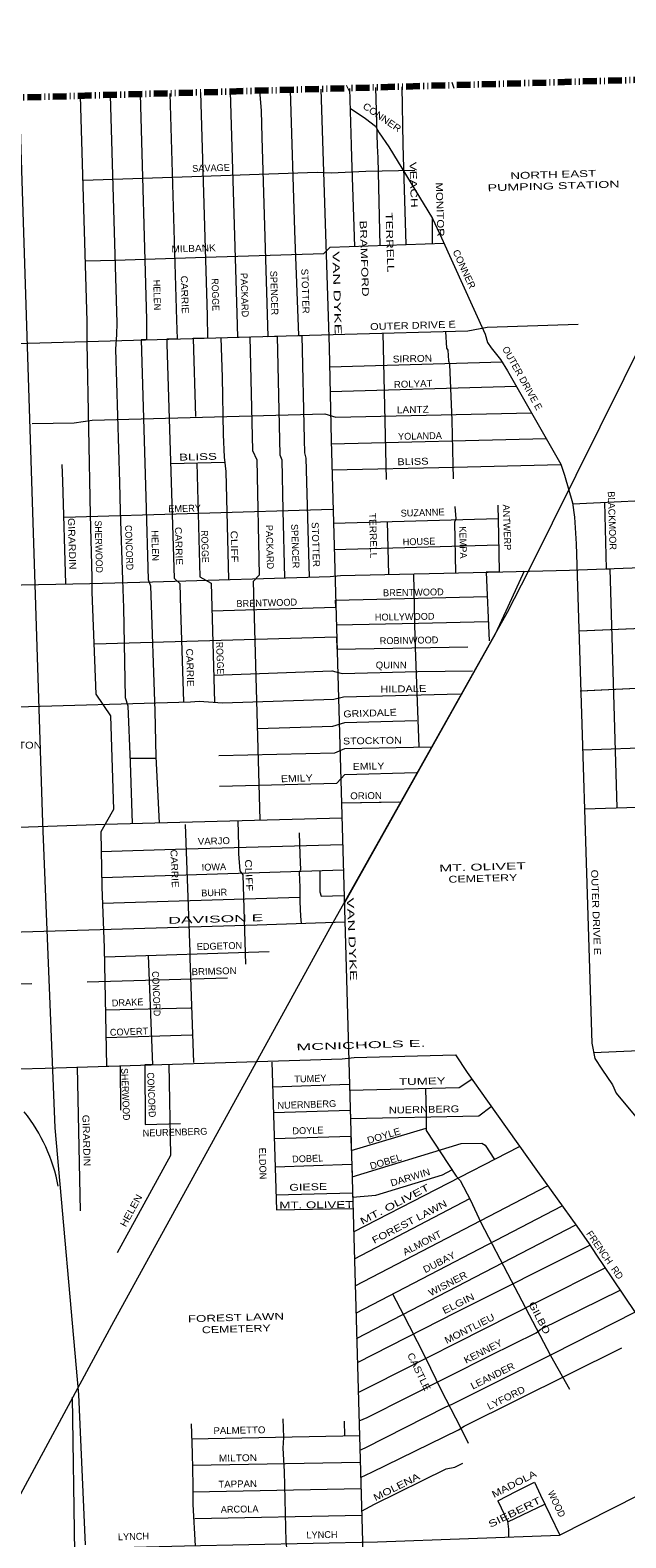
# Model space of a CAD drawing. Extents: x 34705 to 138605, y 34275 to 143551.
# Drawn here: x 102735 to 109243, y 126812 to 143301 of the extents above; entities that cross this region are included whole.
import ezdxf
from ezdxf.enums import TextEntityAlignment as Align

# ---------------------------------------------------------------- set-up
doc = ezdxf.new("R2010")
doc.units = 0
doc.header["$LTSCALE"] = 30
doc.linetypes.add('DASH_DOUBLE_DOT', pattern=[9.2, 5, -1.2, 0.3, -1.2, 0.3, -1.2])
for name, color, linetype, lineweight in [('1', 7, 'Continuous', 13), ('11', 7, 'Continuous', 13), ('50', 7, 'Continuous', 13), ('59', 7, 'DASH_DOUBLE_DOT', 106)]:
    doc.layers.add(name, color=color, linetype=linetype, lineweight=lineweight)

msp = doc.modelspace()

# ---------------------------------------------------------------- linework, layer by layer
at = {"layer": '1'}
for p, q in [((105241.22, 142636.71), (105241.23, 142636.69)), ((105577.19, 142646.29), (105577.19, 142646.27)), ((106225.39, 142664.78), (106225.39, 142664.76)), ((106509.93, 142672.9), (106509.93, 142672.88)), ((106798.42, 142681.13), (106798.42, 142681.11)), ((103282.09, 142580.82), (103282.09, 142580.81)), ((103608.22, 142590.12), (103608.22, 142590.11)), ((103936.04, 142599.48), (103936.04, 142599.46)), ((104597.13, 142618.33), (104597.13, 142618.32)), ((107125.24, 141252.45), (107125.24, 140965.6)), ((106588.83, 139987.07), (106625.18, 138387.12)), ((106006.47, 139620.57), (107895.32, 139674.21)), ((106011.62, 139347.51), (108047.5, 139407.06)), ((106022.69, 138778.23), (108372.47, 138836.55)), ((104269.01, 138562.85), (104861.84, 138574.95)), ((103104.63, 137975.65), (106043.11, 138062.79)), ((106047.45, 137910.61), (107847.77, 137958.8)), ((106636.48, 137926.38), (106648.38, 137348.73)), ((106055.76, 137619.77), (107853.69, 137673.55)), ((108770.55, 135431.09), (111396.79, 135518.47)), ((103831.38, 135339.63), (104104.63, 135339.63)), ((106134.79, 134850.9), (106755.8, 134862.73)), ((106145.33, 134851.1), (106780.48, 134863.2)), ((103520.34, 134033.98), (106155.73, 134117.16)), ((103526.15, 133754.82), (105679.75, 133819.22)), ((103549.41, 133167.42), (105345.92, 133225.58)), ((103359.03, 132891.89), (104891.72, 132937.53)), ((101502.89, 132835.92), (102751.71, 132874.45)), ((103564.13, 132283.14), (104502.9, 132312.49)), ((103248.56, 131961.25), (103281.01, 130390.15)), ((106268.74, 130157.86), (108081.19, 131092.77)), ((106285.57, 129568.32), (108387.63, 130663.68)), ((106277.11, 129864.47), (107537.35, 130523.14)), ((106294.05, 129271.02), (108547.04, 130441.73)), ((106302.01, 128992.23), (108696.67, 130233.82)), ((106166.78, 128088.93), (106167.87, 127927.46)), ((104499.25, 127896.76), (106332.27, 127932.02)), ((104507.95, 127606.16), (106340.57, 127641.41)), ((104511.93, 127315.08), (106348.87, 127350.42)), ((107952.24, 126985.55), (108358.24, 127182.27)), ((104534.64, 127024.47), (106357.17, 127059.53))]:
    msp.add_line(p, q, dxfattribs=at)
for points in [[(105240.21, 142636.66), (105258.81, 142422.75), (105265.22, 142127.75), (105330.55, 139952.31), (105434.27, 139955.26), (105463.96, 138658.25), (105483.19, 138600.53), (105496.02, 138049), (105515.21, 137309.76)], [(105576.18, 142646.24), (105624.24, 141108.06), (105666.52, 139961.86), (105704.77, 139962.95), (105726.81, 138824.99), (105733.22, 138677.49), (105746.05, 138619.77), (105784.05, 137317.69)], [(105908.84, 142655.73), (106002.49, 139831.85), (106021.72, 138812.17), (106489.73, 122415.45), (106528.19, 121498.37), (106553.84, 121113.59), (107079.54, 120098.72), (107093.68, 120071.85)], [(106224.37, 142664.73), (106241.41, 142042.82), (106247.23, 141909.04), (106276.87, 140936.34)], [(106508.91, 142672.85), (106526.33, 142037.01), (106532.15, 141903.22), (106555.92, 140945.96)], [(106797.4, 142681.08), (106805.43, 142054.46), (106811.25, 141920.67), (106840.66, 140955.79)], [(103281.07, 142580.78), (103353.13, 140117.24), (103354.28, 139882.14), (103389.99, 137999.3), (103409.23, 137316.31), (103409.23, 137155.99), (103454.1, 136040.1), (103614.38, 135802.82), (103646.44, 134776.72), (103505.39, 134533.02), (103518.22, 133930.18), (103543.86, 133266.43), (103569.91, 131971.03), (103716.95, 131975.49), (103722.94, 131489.9)], [(103607.2, 142590.08), (103680.1, 140098), (103678.49, 139972.94), (103665.67, 139812.61), (103710.55, 138355.24), (103716.96, 138041), (103742.6, 137290.66), (103755.42, 136982.83), (103774.66, 136001.62), (103800.3, 135911.84), (103827.55, 135292.98), (103850.48, 134623.9)], [(103935.02, 142599.43), (104007.06, 140136.48), (104005.18, 139914.61), (103946.92, 139912.95), (103999.04, 138198.11), (104024.69, 137293.86), (104050.33, 137223.32), (104095.21, 135854.12), (104108.03, 135353.9), (104144.4, 134632.18)], [(104261.52, 142608.74), (104334.02, 140130.07), (104340.55, 139924.15), (104229.28, 139920.98), (104229.84, 139865.52), (104306.77, 137306.69), (104370.88, 137248.97), (104377.3, 136966.79), (104409.24, 135953.78)], [(104596.11, 142618.29), (104667.4, 140181.37), (104672.31, 139933.59), (104515.43, 139929.12), (104540.84, 139076.62)], [(104921.4, 142627.57), (104994.36, 140200.61), (105000.11, 139942.91), (105133.99, 139946.72), (105165.85, 138704.75), (105210.73, 138602.14), (105236.38, 137338.75), (105172.26, 137271.42), (105223.55, 135443.68), (105243.22, 134663.15)], [(106230.31, 142447.99), (106398.41, 142333.65), (106508.89, 142252.22), (106549.59, 142176.6), (106654.25, 142025.37), (107131.06, 141240.14), (107229.91, 141030.74), (107706.71, 139977.94), (107729.97, 139884.88), (107770.67, 139826.71), (107875.33, 139698.75), (107950.92, 139576.6), (108532.39, 138555.8), (108573.09, 138433.65), (108660.31, 138131.19), (108683.57, 137974.15), (108701.02, 137683.32), (108869.64, 132221.58), (108904.53, 132052.9), (108980.12, 131936.57), (109096.41, 131767.89), (109137.12, 131674.83), (109369.7, 131394.19)], [(103313.94, 141659.99), (104290.68, 141694.88), (105872.08, 141747.22), (106023.24, 141741.41), (106401.15, 141758.85), (106936.03, 141770.49)], [(103343.01, 140778.89), (103662.77, 140784.71), (104651.15, 140819.6), (105941.85, 140857.4), (106011.61, 140927.19), (107257.34, 140970.16)], [(90124.26, 139559.75), (94346.64, 139649.89), (98992, 139772.02), (106174.4, 139976.31), (107517.43, 140011.2), (107726.73, 140051.91), (108720.92, 140086.81)], [(107273.19, 140004.85), (107282.24, 139823.81), (107299.68, 139800.54), (107305.5, 139684.21), (107317.13, 139649.31), (107340.38, 139032.76), (107352.01, 138549.98), (107357.83, 138392.94)], [(104817.86, 139937.72), (104832.48, 139506.39), (104845.3, 138877.9), (104855.55, 138630.68), (104873.28, 138473.62), (104902.91, 137291.71)], [(102755.8, 138999.24), (103215.15, 139005.59), (103412.77, 139034.14), (105953.47, 139103.93), (105953.47, 139103.93), (106075.57, 139069.03), (108213.42, 139115.78)], [(103082.26, 138550.83), (103087.08, 138369.66), (103119.91, 137244.96)], [(104555.29, 138568.69), (104588.86, 137322.73), (104710.67, 137252.18), (104748.75, 135950.51)], [(106030.82, 138493.3), (107366.27, 138522.34), (108533.51, 138552.44)], [(108664.22, 138121.05), (109867.71, 138179.21), (111303.76, 138237.37), (111320.11, 138237.28), (111322.59, 138165.33), (114938.93, 138286.81), (115270.33, 138298.44), (115421.49, 138315.89), (115595.91, 138344.97), (115793.58, 138379.86), (116002.89, 138408.94), (116590.1, 138426.39), (116700.56, 138420.57), (118925.85, 138493.26), (119005.88, 138494.1), (118966.04, 138412.22), (119013.06, 138411.84), (121049.49, 138481.62), (122550.35, 138528.72)], [(107375.27, 138090.48), (107386.9, 137956.7), (107369.46, 137921.8), (107381.16, 137365.65)], [(107844.24, 138107.91), (107852.08, 137776.38), (107858.06, 137376.67), (107717.8, 137373.43), (107749.55, 136622.18)], [(109008.41, 138137.68), (109026.36, 137409.71), (109067.79, 137410.34), (109143.51, 134796.33)], [(89232.24, 136885.29), (90112.2, 136931.38), (91366.5, 136935.99), (91366.5, 136935.99), (92803.93, 136935.99), (93200.15, 136949.81), (94080.12, 136972.86), (96283.49, 137037.38), (97052.88, 137051.21), (97647.21, 137074.25), (99279.05, 137128.15), (100742.47, 137173.13), (101449.66, 137193.58), (102455.25, 137230.38), (103387.26, 137250.83), (104070.94, 137267.18), (106012.63, 137324.43), (106127.09, 137336.7), (107898.11, 137377.59), (108625.74, 137393.94), (111271.54, 137492.08)], [(108133.14, 137382.87), (107955.18, 136995.41), (107817.1, 136696.16), (106166.26, 133748.33)], [(106921.39, 137355.04), (106939.17, 136649.43), (106979.87, 135462.85)], [(104719.52, 136949.85), (106073.67, 136992.01), (106071.57, 137065.46), (107726.73, 137107.65)], [(106079.23, 136797.06), (106976.73, 136816.86), (107740.56, 136834.49)], [(108730.42, 136730.91), (110361.9, 136800.85), (111368.15, 136842.06)], [(108733.99, 136731.06), (110361.9, 136800.85), (111356.09, 136841.56)], [(103436.03, 136590.04), (106082.95, 136666.72), (106086.82, 136531.37), (107515.21, 136557.33)], [(104744.17, 136246.9), (106029.05, 136293.43), (106034.87, 136293.43), (106127.89, 136270.17), (106145.33, 136264.35), (106970.92, 136287.62), (107568.73, 136293.98)], [(92946.94, 135660.23), (93342.28, 135666.05), (93342.28, 135660.23), (93505.08, 135747.47), (95619.1, 135806.18), (95623.65, 135694.55), (97684.58, 135762.73), (99091.56, 135791.81), (100777.6, 135844.15), (100969.46, 135844.15), (102463.65, 135896.5), (104488.36, 135956.11), (104581.38, 135961.93), (104837.19, 135944.48), (106052.31, 135985.19), (106156.96, 136008.45), (107431.31, 136044.53)], [(108745.62, 136076.79), (109745.62, 136123.31), (110704.92, 136164.02), (111390.97, 136181.47)], [(108750.61, 136077.02), (109745.62, 136123.31), (110704.92, 136164.02), (111390.9, 136181.47)], [(105217.33, 135665.05), (106040.68, 135688.58), (106174.4, 135729.29), (106959.29, 135752.56)], [(104796.5, 135368.71), (106063.94, 135397.79), (106174.4, 135444.32), (107110.18, 135461.65)], [(104802.31, 135031.39), (106087.19, 135066.29), (106174.4, 135159.34), (106956.49, 135182.69)], [(108790.49, 134785.25), (115475.27, 134995.04), (117335.18, 135061.27)], [(108890.69, 132119.83), (110218.62, 132177.59), (111463.66, 132219.8), (111598.19, 132244.87), (113708.42, 133273.94), (116745.85, 134738.39), (117107.22, 134743.67), (117260.22, 134791.17), (117560.93, 134785.89), (119249.54, 134800.95), (119957.59, 134818.33), (120035.78, 134827.02), (120789.59, 134833.38), (121930.43, 134865.05), (122072.88, 134859.77), (123502.56, 134875.6), (123708.58, 134772.56)], [(83101.01, 133486.56), (83891.71, 133858.78), (85025.43, 133905.3), (85083.57, 133934.38), (86840.83, 134002.71), (86990.55, 133998.36), (87997.81, 134043.42), (88660.6, 134066.69), (89340.84, 134089.95), (89858.28, 134107.4), (90311.77, 134159.74), (90515.26, 134258.61), (90840.84, 134305.14), (93673.68, 134351.66), (95138.8, 134363.3), (95679.5, 134380.74), (97726.73, 134441.09), (98308.13, 134452.72), (100831.39, 134522.51), (103555.22, 134615.57), (106139.42, 134688.42)], [(104428.58, 134613.19), (104479.87, 133221.54), (104479.87, 133151), (104518.34, 132009.46)], [(105004.8, 134656.43), (105011.99, 134375.9), (105011.99, 134292.53), (105024.81, 134106.55), (105056.87, 134061.66), (105087.62, 133085.11)], [(103508.71, 134318.96), (104438.94, 134348.04), (106147.79, 134395.33)], [(105675.53, 134523.4), (105681.94, 134286.12), (105688.35, 134119.38), (105675.53, 134087.31), (105681.94, 133926.98), (105681.94, 133766.66), (105688.35, 133612.74), (105695.63, 133532.55)], [(105899.91, 134109.09), (105899.91, 133875.68), (105912.73, 133830.79), (106163.72, 133837.39)], [(95130.25, 130321.18), (95381.61, 130325.96), (95576.64, 130393.64), (96452.28, 130819.66), (97383.65, 131301.42), (98108.05, 131675.68), (101094.19, 133205.57), (101336.98, 133321.03), (101452.41, 133392.7), (101671.32, 133392.7), (102639.49, 133440.47), (105214.69, 133516.12), (106171.95, 133548.83)], [(104024.82, 133182.81), (104071.67, 131986.28), (103986.02, 131983.68), (103992.63, 131331.27), (104377.3, 131344.1)], [(103561.03, 132585.84), (104485.45, 132609.1), (104491.27, 132609.1)], [(89151.86, 131581.25), (90043.44, 131623.47), (90222.81, 131655.13), (92165.54, 131723.74), (95067.12, 131739.57), (95420.59, 131739.57), (95721.29, 131755.4), (98262.81, 131813.45), (98568.79, 131829.28), (100441.63, 131866.22), (101676.12, 131897.89), (102335.57, 131934.83), (102900.06, 131950.66), (106145.2, 132049.31), (106275.51, 132066.69), (107380.6, 132092.9)], [(107380.6, 132092.9), (107509.01, 131900.23), (107729.97, 131586.13), (108276.55, 130818.35), (108706.83, 130219.24), (108840.57, 130027.3), (108921.97, 129905.15), (109090.6, 129655.04), (109352.26, 129265.33), (109520.89, 129026.85), (109672.07, 128817.45), (109799.99, 128637.14), (110038.39, 128323.04), (110347.56, 127910.69)], [(104248.73, 131991.66), (104268.31, 130992.99), (103685.3, 129928.8)], [(105374.21, 132014.28), (105425.49, 130398.17), (106015.31, 130411), (106261.38, 130415.72)], [(105382.78, 131744.16), (106222.62, 131773.5), (106224.5, 131707.7), (107422.29, 131736.45), (107559.04, 131829.11)], [(107055.03, 131728), (107061.28, 131446.54), (107061.28, 131312.75), (107061.28, 131266.22), (107389.18, 130767.47), (107434.67, 130721.97), (107545.84, 130504.6), (107657.02, 130261.95), (107990.55, 129625), (108420.1, 128806.07), (108627.29, 128437.04)], [(105391.72, 131462.33), (106230.7, 131490.67), (106233.29, 131399.77), (107635.14, 131427.93), (107769.83, 131530.14)], [(105400.68, 131180.2), (106238.88, 131203.93), (106243.3, 131049.26), (107061.28, 131293.95)], [(105410.48, 130871.28), (106247.54, 130900.63), (106251.58, 130758.89), (107444.01, 131123.76), (107669.89, 131128.11), (107704.65, 131106.38), (107806.52, 130951.09)], [(105420.26, 130563.11), (106256.49, 130587.1), (106257.89, 130538), (106510.08, 130558.88), (107239.85, 130780.49), (107343.46, 130837.02)], [(106309.47, 128731), (107389.34, 129281.12), (108850.73, 130012.05)], [(106324.83, 128403.6), (106477.61, 128482.48), (108005.37, 129256.47), (108291.21, 129399.43), (109015.35, 129766.65)], [(106327.76, 128090.16), (106418.47, 128127.53), (107758.96, 128807.85), (108261.64, 129054.34), (108315.85, 129093.78), (109180.46, 129521.2)], [(106695.19, 129479.47), (106817.06, 129242.06), (106875.21, 129131.55), (107049.65, 128788.37), (107224.09, 128427.74), (107433.42, 128026.4), (107520.64, 127846.09)], [(106336.86, 127771.32), (106393.83, 127797.22), (107275.99, 128245.84), (107344.98, 128275.42), (108379.92, 128793.06), (108453.85, 128827.57), (109342.27, 129279.46)], [(106345.39, 127472.47), (106467.75, 127531.01), (107413.98, 127994.42), (107478.05, 128033.86), (109198.02, 128891.66)], [(104492.69, 128060.59), (104505.52, 127739.94), (104511.93, 127387.22), (104511.93, 127175.58), (104538.35, 126726.21)], [(105496.02, 128113.5), (105502.43, 127908.28), (105496.02, 127792.85), (105508.84, 127536.32), (105528.07, 126773.16), (105540.89, 126670.55), (105540.89, 126484.57), (105553.72, 126119.02), (105983.26, 126131.85), (106383.49, 126137.66), (106382.09, 126186.48), (106858.57, 126206.46)], [(103316.6, 126694.24), (104421.29, 126723.75), (106530.59, 126768.12), (108517.91, 126840.83), (110257.59, 127723.28), (110321.66, 127807.08), (110347.56, 127910.69)], [(106355.88, 127104.81), (106497.32, 127180.99), (107280.92, 127565.52), (107374.55, 127585.24), (107463.26, 127629.61)], [(107846.01, 127216.97), (108049.73, 127323.96), (108243.48, 127422.56)], [(108243.48, 127422.56), (108311.43, 127280.44), (108520.42, 126842.1)], [(107846.01, 127216.97), (107950.92, 126995.42), (107962.55, 126908.18), (107962.55, 126820.51)]]:
    msp.add_lwpolyline(points, dxfattribs=at)
at = {"layer": '50'}
msp.add_line((103193.88, 128351.06), (103217.66, 126651.13), dxfattribs=at)
for points in [[(102381.37, 126834.33), (103625.89, 129138.56), (106032.14, 133515.49), (107949.49, 136936.41), (108177.8, 137385.22), (110790.54, 142647.36)], [(103340.26, 126734.43), (103267.19, 128379.83), (103009.15, 131294.52), (102874.51, 134633.08), (102617.68, 142561.85)]]:
    msp.add_lwpolyline(points, dxfattribs=at)
msp.add_arc((101213, 130316.33), 1860.19, 10.55696, 38.38477, dxfattribs=at)
at = {"layer": '59'}
msp.add_lwpolyline([(131989.06, 109708.72), (126856.28, 120352.83), (127983.73, 120601.28), (129321.71, 120998.46), (130612.42, 121494.12), (133722.19, 123216.65), (134563.84, 124776.42), (136438.38, 130047.1), (136736.54, 131235.05), (136773.12, 131974.15), (125584.57, 138103.26), (128512.62, 143301.1), (34921.35, 140631.52)], dxfattribs=at)

# ---------------------------------------------------------------- texts
at = {"layer": '11'}
for s, rotation, width, p in [('CONNER', 325.489, 1.1, (106558.33, 142316.68)), ('VEACH            ', 271.866, 1.45, (106895.29, 141367.2)), ('PUMPING STATION', 1.665, 1.55, (108454.7, 141560.15)), ('NORTH EAST', 1.665, 1.45, (108451.07, 141685.09)), ('MONITOR  ', 271.865, 1.25, (107176.79, 141303.98)), ('BRAMFORD            ', 271.865, 1.45, (106356.29, 140560.05)), ('TERRELL              ', 271.866, 1.45, (106637.56, 140695.14)), ('MILBANK', 1.698, 1.1, (104521.36, 140876.69)), ('VAN DYKE', 271.7, 1.8, (106050.48, 140425.92)), ('CONNER', 294.365, 1.05, (107442.95, 140672.31)), ('STOTTER', 271.702, 1.05, (105704.89, 140445.69)), ('CARRIE', 271.7, 1.1, (104386.58, 140406.67)), ('ROGGE', 271.7, 0.95, (104721.75, 140407.33)), ('OUTER DRIVE E', 1.714, 1.2, (106918.25, 140034.69)), ('SIRRON', 1.512, 1.1, (106911.73, 139671.28)), ('ROLYAT', 1.865, 1.05, (106920.07, 139395.3)), ('LANTZ', 1.297, 1.1, (106916.12, 139114.24)), ('BLISS       ', 1.526, 1.45, (104710.88, 138601.77)), ('BLISS', 1.36, 1.2, (106917.63, 138546.42)), ('TERRELL', 271.607, 1.1, (106445.36, 137772.56)), ('GIRARDIN', 271.598, 1.15, (103155.37, 137682.7)), ('SHERWOOD', 271.408, 0.95, (103447.4, 137650.95)), ('CONCORD', 271.984, 0.95, (103779.34, 137640.51)), ('CARRIE', 271.644, 1.1, (104322.44, 137658.3)), ('STOTTER', 271.814, 1.05, (105817.93, 137674.78)), ('ROGGE', 271.498, 0.95, (104607.72, 137653.6)), ('CLIFF', 271.528, 1.25, (104929.47, 137652.77)), ('CARRIE', 271.806, 1.1, (104445.21, 136328.45)), ('ROGGE', 272.153, 0.95, (104772.72, 136432.18)), ('HILDALE', 0.998, 1.2, (106812.46, 136060.03)), ('GRIXDALE', 2.001, 1.15, (106449.73, 135794.82)), ('STOCKTON ', 0.999, 1.15, (106490.26, 135494.17)), ('EMILY', 0.999, 1.15, (106432.57, 135213.84)), ('EMILY', 1.883, 1.15, (105648.95, 135081.15)), ('ORION', 0.8, 1.05, (106405.28, 134891.69)), ('VARJO', 1.585, 1.05, (104743.09, 134395.85)), ('CARRIE', 272.3, 1.1, (104275.63, 134129.34)), ('CLIFF', 272.3, 1.25, (105087.6, 134056.64)), ('MT. OLIVET', 1.665, 1.7, (107678.61, 134112.34)), ('CEMETERY', 1.665, 1.35, (107682.24, 133987.39)), ('OUTER DRIVE E', 271.985, 1.2, (108879.69, 133651.3)), ('VAN DYKE', 272.301, 1.8, (106213.62, 133357.48)), ('DAVISON E', 1.683, 1.9, (104763.99, 133542.27)), ('CONCORD', 272.3, 0.95, (104076.08, 132761.84)), ('BRIMSON', 1.705, 1.05, (104745.16, 132972.54)), ('MCNICHOLS E.', 1.741, 1.95, (106350.15, 132163.82)), ('SHERWOOD', 272.3, 0.95, (103739.81, 131661.77)), ('CONCORD', 272.3, 0.95, (104022.89, 131655.35)), ('TUMEY     ', 1.375, 1.45, (107120.65, 131771.13)), ('GIRARDIN', 271.501, 1.15, (103313.02, 131156.98)), ('NUERNBERG  ', 1.151, 1.2, (107072.1, 131460.22)), ('DOYLE', 16.842, 1.1, (106608.8, 131174.29)), ('DOBEL', 16.88, 1.05, (106630.59, 130890.54)), ('DARWIN', 16.849, 1.1, (106897.91, 130719.13)), ('GIESE ', 1.643, 1.35, (105792.95, 130613.19)), ('MT. OLIVET     ', 27.447, 1.5, (106827.16, 130475.91)), ('HELEN', 61.39, 1.15, (103871.11, 130374.03)), ('MT. OLIVET     ', 0.461, 1.45, (105962.38, 130417.94)), ('FOREST LAWN ', 27.448, 1.25, (106911.44, 130242.99)), ('ALMONT', 27.446, 1.1, (107034.18, 130004.36)), ('DUBAY', 27.458, 1.1, (107220.69, 129793.16)), ('WISNER', 27.406, 1.15, (107314.81, 129557.97)), ('ELGIN', 26.572, 1.25, (107428.86, 129341.32)), ('FOREST LAWN', 1.665, 1.45, (104984.21, 129184.76)), ('GILBO', 297.678, 1.25, (108265.84, 129200.7)), ('CEMETERY', 1.665, 1.35, (104987.84, 129059.82)), ('MONTLIEU', 26.868, 1.15, (107552.03, 129067.3)), ('KENNEY', 26.909, 1.1, (107699.55, 128818.21)), ('CASTLE', 295.813, 1.15, (106949.41, 128611.95)), ('LEANDER', 26.573, 1.1, (107803.85, 128549.66)), ('LYFORD', 26.507, 1.1, (107950.5, 128309.9)), ('PALMETTO', 1.001, 1.05, (105021.63, 127951.79)), ('MILTON', 1.002, 1.1, (105005.44, 127648.92)), ('MOLENA  ', 26.5, 1.3, (106786.43, 127351.15)), ('MADOLA ', 27.016, 1.25, (108054.48, 127375.61)), ('TAPPAN', 1.001, 1.05, (105002.43, 127364.56)), ('WOOD', 295.431, 0.95, (108453.07, 127167.69)), ('SIEBERT  ', 26.28, 1.45, (108079.01, 127076.51))]:
    msp.add_text(s, height=75, rotation=rotation, dxfattribs=dict(at, width=width)).set_placement(p, align=Align.CENTER)
for s, rotation, p in [('SAVAGE', 1.699, (104711.93, 141756.83)), ('SPENCER', 271.699, (105364.22, 140426.17)), ('HELEN', 271.699, (104084.11, 140403.3)), ('PACKARD', 271.699, (105040.99, 140403.28)), ('OUTER DRIVE E', 299.193, (108079.5, 139476.45)), ('YOLANDA', 1.298, (106994.16, 138825.37)), ('BLACKMOOR', 271.864, (109055.89, 137935.48)), ('EMERY', 1.728, (104423.19, 138033.11)), ('SUZANNE', 1.803, (107023.28, 137987.82)), ('ANTWERP', 271.999, (107906.99, 137862.13)), ('PACKARD', 271.526, (105316.23, 137647.45)), ('SPENCER', 271.922, (105594.12, 137656.71)), ('KEMPA', 271.605, (107427.45, 137697.18)), ('HELEN', 271.626, (104063.85, 137661.96)), ('HOUSE', 1.616, (106984.24, 137671)), ('BRENTWOOD', 0.999, (106922.26, 137115.34)), ('BRENTWOOD', 1.544, (105321.16, 137000.36)), ('HOLLYWOOD', 1.001, (106827.15, 136848.73)), ('ROBINWOOD', 1.001, (106875.04, 136590.63)), ('IOWA', 1.808, (104743.49, 134111.96)), ('BUHR', 2.299, (104747.01, 133831.95)), ('EDGETON', 1.854, (104804.09, 133247.41)), ('DRAKE', 2.302, (103800.96, 132630.41)), ('COVERT', 2.299, (103816.15, 132310.9)), ('TUMEY', 2.001, (105797.91, 131798.01)), ('NUERNBERG', 1.935, (105758.95, 131514.09)), ('NEURENBERG', 1.705, (104318.42, 131211.25)), ('DOYLE', 1.622, (105771.07, 131230.08)), ('ELDON', 271.438, (105238.63, 130905.34)), ('DOBEL', 2.008, (105768.31, 130923.18)), ('FRENCH  RD', 304.868, (108983.06, 129884.37)), ('ARCOLA', 1, (105024.12, 127089.21)), ('LYNCH', 1.53, (103864.69, 126789.88)), ('LYNCH', 1.285, (105924.04, 126809.13))]:
    msp.add_text(s, height=75, rotation=rotation, dxfattribs=at).set_placement(p, align=Align.CENTER)
for s, width, p in [('QUINN', 1.05, (106679.77, 136320.47)), ('STOCKTON  ', 1.2, (102558.96, 135443.68))]:
    msp.add_text(s, height=75, dxfattribs=dict(at, width=width)).set_placement(p, align=Align.CENTER)

doc.saveas('drawing.dxf')
